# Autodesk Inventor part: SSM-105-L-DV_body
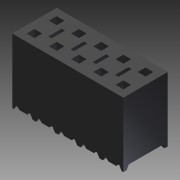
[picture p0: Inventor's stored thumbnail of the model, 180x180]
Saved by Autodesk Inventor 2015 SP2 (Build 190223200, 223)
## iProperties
Category: PARTsolutions
Company: SAMTEC
Created: 2015-08
Part Number: SSM-105-L-DV_body
Catalog Web Link: www.cadenas.de
Description: SSM Series Body-SSM Series - (2,54 mm) .100" Tiger Claw™ Surface Mount Socket
Vendor: SAMTEC
Document SubType Name: Modeling
Designer: PARTuser1
Manufacturer: SAMTEC
Mass: 0.389205 g
Surface Area: 6.51351 cm^2
Volume: 0.389205 cm^3
Density: 1 g/cm^3
Material: Allgemein
Appearance: PSOLRGB-127-127-127
PSOL_IDENT_0: {$CADENAS_DATA\23d-libs\samtec\modelling\ssm\parts\ssm_body.prj},243 {VTYP=3D},{NB=SSM-105-L-DV_body
PSOL_IDENT_1: },{LINA=SSM-105-L-DV_body},{NN=SSM Series Body},{DATE=25.05.2015 10:50:41},{GEOMDATE=25.05.2015 10:4
PSOL_IDENT_2: 9:00},{VERSION=},{LINEID=10},{LINESUBID=-1},{WBVAR=POS,ROW,PLOPT,BEOPT,LCOPT,POLOPT,AOPT,POPT,MOPT,K
PSOL_IDENT_3: OPT,TROPT}  {NB=SSM-105-L-DV_body},{LINA=SSM-105-L-DV_body},{KT=DUMMY},{PN=SSM-105-L-DV},{SERIES=SSM
PSOL_IDENT_4: },{POS=5},{POSPN=05},{ROW=-DV},{ROWALG= '-SV','-SV - Single Vertical','-SH','-SH - Single Horizontal'
PSOL_IDENT_5: ,'-DH','-DH - Double Horizontal','-DV','-DV - Double Vertical' },{PLOPT=-L},{PLOPTALG= '-S','-S - 30
PSOL_IDENT_6: micro\" Selective Gold in Contact Area, Matte Tin on Tail','-L','-L - 10micro\" Light Selective Gold
PSOL_IDENT_7: in Contact Area, Matte Tin on Tail','-T','-T - Matte Tin Contact and Tail','-F','-F - 3micro\" Flas
PSOL_IDENT_8: h Selective Gold Contact, Matte Tin on Tail','-H','-H - 30micro\" Heavy Gold in Contact Area, 3micro
PSOL_IDENT_9: \" on Tail','-STL','-STL - 30micro\" Selective Gold in Contact Area, Tin/Lead (90/10+/-5%) Tail','-S
PSOL_IDENT_10: M','-SM - 30micro\" Selective Gold in Contact Area, Matte Tin on Tail','-LM','-LM - 10micro\" Light
PSOL_IDENT_11: Selective Gold in Contact Area, Matte Tin Tail','-TM','-TM - Matte Tin Contact and tail','-FM','-FM
PSOL_IDENT_12: - 3micro\" Flash Selective Gold in Contact Area, Matte Tin Tail' },{BEOPT=},{BEOPTALG= '','Not Selec
PSOL_IDENT_13: ted','-BE','-BE - Bottom Entry' },{LCOPT=},{LCOPTALG= '','Not Selected','-LC','-LC Locking Clip' },{
PSOL_IDENT_14: POLOPT=},{POLOPTALG= '','Not Selected','001','001','002','002','003','003','004','004','005','005','
PSOL_IDENT_15: 006','006','007','007','008','008','009','009','010','010' },{POLOPTMAX=120},{POLOPTMAX2='001','001'
PSOL_IDENT_16: ,'002','002','003','003','004','004','005','005','006','006','007','007','008','008','009','009','01
PSOL_IDENT_17: 0','010'},{POLARIZE='001','001','002','002','003','003','004','004','005','005','006','006','007','0
PSOL_IDENT_18: 07','008','008','009','009','010','010','011','011','012','012','013','013','014','014','015','015','
PSOL_IDENT_19: 016','016','017','017','018','018','019','019','020','020','021','021','022','022','023','023','024'
PSOL_IDENT_20: ,'024','025','025','026','026','027','027','028','028','029','029','030','030','031','031','032','03
PSOL_IDENT_21: 2','033','033','034','034','035','035','036','036','037','037','038','038','039','039','040','040','
PSOL_IDENT_22: 041','041','042','042','043','043','044','044','045','045','046','046','047','047','048','048','049'
PSOL_IDENT_23: ,'049','050','050','051','051','052','052','053','053','054','054','055','055','056','056','057','05
PSOL_IDENT_24: 7','058','058','059','059','060','060','061','061','062','062','063','063','064','064','065','065','
PSOL_IDENT_25: 066','066','067','067','068','068','069','069','070','070','071','071','072','072','073','073','074'
PSOL_IDENT_26: ,'074','075','075','076','076','077','077','078','078','079','079','080','080'},{POLOPTATOF=0},{POLO
PSOL_IDENT_27: PTPN=},{AOPT=},{AOPTALG= '','Not Selected','-A','-A - Alignment Pin' },{POPT=},{POPTALG= '','Not Sel
PSOL_IDENT_28: ected','-P','-P - Pick & Place Pad' },{MOPT=},{MOPTALG= '','Not Selected','-M','-M - Metal Pick & Pl
PSOL_IDENT_29: ace Pad' },{KOPT=},{KOPTALG= '','Not Selected','-K','-K - Polyimide Film Pad' },{TROPT=},{TROPALG= ''
PSOL_IDENT_30: ,'Not Selected','-TR','-TR - Tape & Reel'  },{OE=1},{S=0.00250},{SK=0.12200},{SM=0.13050},{POLOE=2}
NN: SSM Series Body
NT: SSM Series - (2,54 mm) .100" Tiger Claw™ Surface Mount Socket
NB: SSM-105-L-DV_body
NBSYN: $PN._body
LINA: SSM-105-L-DV_body
SERIES: SSM
POS: 5
ROW: -DV - Double Vertical
PLOPT: -L - 10micro" Light Selective Gold in Contact Area, Matte Tin on Tail
BEOPT: Not Selected
LCOPT: Not Selected
POLOPT: Not Selected
AOPT: Not Selected
POPT: Not Selected
MOPT: Not Selected
KOPT: Not Selected
TROPT: Not Selected
SUPPLIER: SAMTEC
ARTICLENO: SSM-105-L-DV_body
BOMINFO: SSM-105-L-DV_body
CREATOR: CADENAS GmbH
Title: SSM-105-L-DV_body
Author: Cadenas PARTsolutions
Comments: SSM Series - (2,54 mm) .100" Tiger Claw™ Surface Mount Socket
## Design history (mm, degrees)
sketch "Sketch_1"
  geometry: L1 (6.35, -2.54)-(6.35, 2.54); L2 (6.35, 2.54)-(-6.35, 2.54); L3 (-6.35, 2.54)-(-6.35, -2.54); L4 (-6.35, -2.54)-(6.35, -2.54); L5 (-4.636, 0.826)-(-4.636, 1.714); L6 (-4.636, 1.714)-(-5.524, 1.714); L7 (-5.524, 1.714)-(-5.524, 0.826); L8 (-5.524, 0.826)-(-4.636, 0.826); L9 (-4.636, -1.714)-(-4.636, -0.826); L10 (-4.636, -0.826)-(-5.524, -0.826); L11 (-5.524, -0.826)-(-5.524, -1.714); L12 (-5.524, -1.714)-(-4.636, -1.714); L13 (-2.096, 0.826)-(-2.096, 1.714); L14 (-2.096, 1.714)-(-2.985, 1.714); L15 (-2.985, 1.714)-(-2.985, 0.826); L16 (-2.985, 0.826)-(-2.096, 0.826); L17 (-2.096, -1.714)-(-2.096, -0.826); L18 (-2.096, -0.826)-(-2.985, -0.826); L19 (-2.985, -0.826)-(-2.985, -1.714); L20 (-2.985, -1.714)-(-2.096, -1.714); L21 (0.445, 0.826)-(0.445, 1.714); L22 (0.445, 1.714)-(-0.445, 1.714); L23 (-0.445, 1.714)-(-0.445, 0.826); L24 (-0.445, 0.826)-(0.445, 0.826); L25 (0.445, -1.714)-(0.445, -0.826); L26 (0.445, -0.826)-(-0.445, -0.826); L27 (-0.445, -0.826)-(-0.445, -1.714); L28 (-0.445, -1.714)-(0.445, -1.714); L29 (2.985, 0.826)-(2.985, 1.714); L30 (2.985, 1.714)-(2.096, 1.714); L31 (2.096, 1.714)-(2.096, 0.826); L32 (2.096, 0.826)-(2.985, 0.826); L33 (2.985, -1.714)-(2.985, -0.826); L34 (2.985, -0.826)-(2.096, -0.826); L35 (2.096, -0.826)-(2.096, -1.714); L36 (2.096, -1.714)-(2.985, -1.714); L37 (5.524, 0.826)-(5.524, 1.714); L38 (5.524, 1.714)-(4.636, 1.714); L39 (4.636, 1.714)-(4.636, 0.826); L40 (4.636, 0.826)-(5.524, 0.826); L41 (5.524, -1.714)-(5.524, -0.826); L42 (5.524, -0.826)-(4.636, -0.826); L43 (4.636, -0.826)-(4.636, -1.714); L44 (4.636, -1.714)-(5.524, -1.714)
  constraints: 88 end point
extrude "Extrusion1" join sketch "Sketch_1" distance "d0" = 7.366; taper "d1" = 0 deg
sketch "Sketch_3"
  geometry: L1 (0, 2.184)-(-0.254, 2.184); L2 (-0.254, 2.184)-(-0.254, -2.184); L3 (-0.254, -2.184)-(0, -2.184); L4 (0, -2.184)-(0.457, -1.92); L5 (0.457, -1.92)-(0.457, 1.92); L6 (0.457, 1.92)-(0, 2.184)
  constraints: 12 end point
extrude "Extrusion2" cut sketch "Sketch_3" stored distance "d2" = 25.4; taper "d3" = 0 deg
sketch "Sketch_2"
  geometry: L1 (-6.315, -2.54)-(95.215, -2.54); L2 (95.215, -2.54)-(95.215, -0.254); L3 (95.215, -0.254)-(94.78, 0.457); L4 (94.78, 0.457)-(94.653, 0.457); L5 (94.653, 0.457)-(94.424, 0.203); L6 (94.424, 0.203)-(93.535, 0.203); L7 (93.535, 0.203)-(93.307, 0.457); L8 (93.307, 0.457)-(93.18, 0.457); L9 (93.18, 0.457)-(92.745, -0.254); L10 (92.745, -0.254)-(92.675, -0.254); L11 (92.675, -0.254)-(92.24, 0.457); L12 (92.24, 0.457)-(92.113, 0.457); L13 (92.113, 0.457)-(91.885, 0.203); L14 (91.885, 0.203)-(90.996, 0.203); L15 (90.996, 0.203)-(90.767, 0.457); L16 (90.767, 0.457)-(90.64, 0.457); L17 (90.64, 0.457)-(90.205, -0.254); L18 (90.205, -0.254)-(90.135, -0.254); L19 (90.135, -0.254)-(89.7, 0.457); L20 (89.7, 0.457)-(89.573, 0.457); L21 (89.573, 0.457)-(89.344, 0.203); L22 (89.344, 0.203)-(88.456, 0.203); L23 (88.456, 0.203)-(88.227, 0.457); L24 (88.227, 0.457)-(88.1, 0.457); L25 (88.1, 0.457)-(87.665, -0.254); L26 (87.665, -0.254)-(87.595, -0.254); L27 (87.595, -0.254)-(87.16, 0.457); L28 (87.16, 0.457)-(87.033, 0.457); L29 (87.033, 0.457)-(86.805, 0.203); L30 (86.805, 0.203)-(85.915, 0.203); L31 (85.915, 0.203)-(85.687, 0.457); L32 (85.687, 0.457)-(85.56, 0.457); L33 (85.56, 0.457)-(85.125, -0.254); L34 (85.125, -0.254)-(85.055, -0.254); L35 (85.055, -0.254)-(84.62, 0.457); L36 (84.62, 0.457)-(84.493, 0.457); L37 (84.493, 0.457)-(84.265, 0.203); L38 (84.265, 0.203)-(83.376, 0.203); L39 (83.376, 0.203)-(83.147, 0.457); L40 (83.147, 0.457)-(83.02, 0.457); L41 (83.02, 0.457)-(82.585, -0.254); L42 (82.585, -0.254)-(82.515, -0.254); L43 (82.515, -0.254)-(82.08, 0.457); L44 (82.08, 0.457)-(81.953, 0.457); L45 (81.953, 0.457)-(81.725, 0.203); L46 (81.725, 0.203)-(80.836, 0.203); L47 (80.836, 0.203)-(80.607, 0.457); L48 (80.607, 0.457)-(80.48, 0.457); L49 (80.48, 0.457)-(80.045, -0.254); L50 (80.045, -0.254)-(79.975, -0.254); L51 (79.975, -0.254)-(79.54, 0.457); L52 (79.54, 0.457)-(79.413, 0.457); L53 (79.413, 0.457)-(79.184, 0.203); L54 (79.184, 0.203)-(78.296, 0.203); L55 (78.296, 0.203)-(78.067, 0.457); L56 (78.067, 0.457)-(77.94, 0.457); L57 (77.94, 0.457)-(77.505, -0.254); L58 (77.505, -0.254)-(77.435, -0.254); L59 (77.435, -0.254)-(77, 0.457); L60 (77, 0.457)-(76.873, 0.457); L61 (76.873, 0.457)-(76.644, 0.203); L62 (76.644, 0.203)-(75.755, 0.203); L63 (75.755, 0.203)-(75.527, 0.457); L64 (75.527, 0.457)-(75.4, 0.457)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
  constraints: 644 end point
extrude "Extrusion3" cut sketch "Sketch_2" stored distance "d4" = 5.08; taper "d5" = 0 deg
sketch "Sketch_24"
  geometry: L1 (-4.001, 7.747)-(-4.001, 5.207); L2 (-4.001, 5.207)-(-3.619, 5.207); L3 (-3.619, 5.207)-(-3.619, 7.366); L4 (-3.619, 7.366)-(-1.46, 7.366); L5 (-1.46, 7.366)-(-1.46, 5.207); L6 (-1.46, 5.207)-(-1.079, 5.207); L7 (-1.079, 5.207)-(-1.079, 7.366); L8 (-1.079, 7.366)-(1.079, 7.366); L9 (1.079, 7.366)-(1.079, 5.207); L10 (1.079, 5.207)-(1.46, 5.207); L11 (1.46, 5.207)-(1.46, 7.366); L12 (1.46, 7.366)-(3.619, 7.366); L13 (3.619, 7.366)-(3.619, 5.207); L14 (3.619, 5.207)-(4.001, 5.207); L15 (4.001, 5.207)-(4.001, 7.747); L16 (4.001, 7.747)-(-4.001, 7.747)
  constraints: 32 end point
extrude "Extrusion4" cut sketch "Sketch_24" stored distance "d6" = 1.524; taper "d7" = 0 deg
node "body_XY"
node "body_YZ"
node "body_ZX"
node "body_X"
node "body_Y"
node "body_Z"
node "body_Center"
node "terminal_XY"
node "terminal_YZ"
node "terminal_ZX"
node "terminal_X"
node "terminal_Y"
node "terminal_Z"
node "terminal_Center"
body "Solid1"
